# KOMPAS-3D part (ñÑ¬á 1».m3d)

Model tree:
1. Эскиз:1
2. Операция выдавливания:1
     Расстояние 1 = 0.6
3. Эскиз:2
4. Вырезать элемент выдавливания:1
     Толщина стенки 1 = 3; Толщина стенки 2 = 3; Расстояние 1 = 10
5. Эскиз:3
6. Вырезать элемент выдавливания:2
     Толщина стенки 1 = 3; Толщина стенки 2 = 3; Расстояние 1 = 10
7. Эскиз:4
8. Вырезать элемент выдавливания:3
     Толщина стенки 1 = 3; Толщина стенки 2 = 3; Расстояние 1 = 10
9. Эскиз:5
10. Вырезать элемент выдавливания:4
     Толщина стенки 1 = 3; Толщина стенки 2 = 3; Расстояние 1 = 10
11. Эскиз:6
12. Вырезать элемент выдавливания:5
     Расстояние 1 = 10
